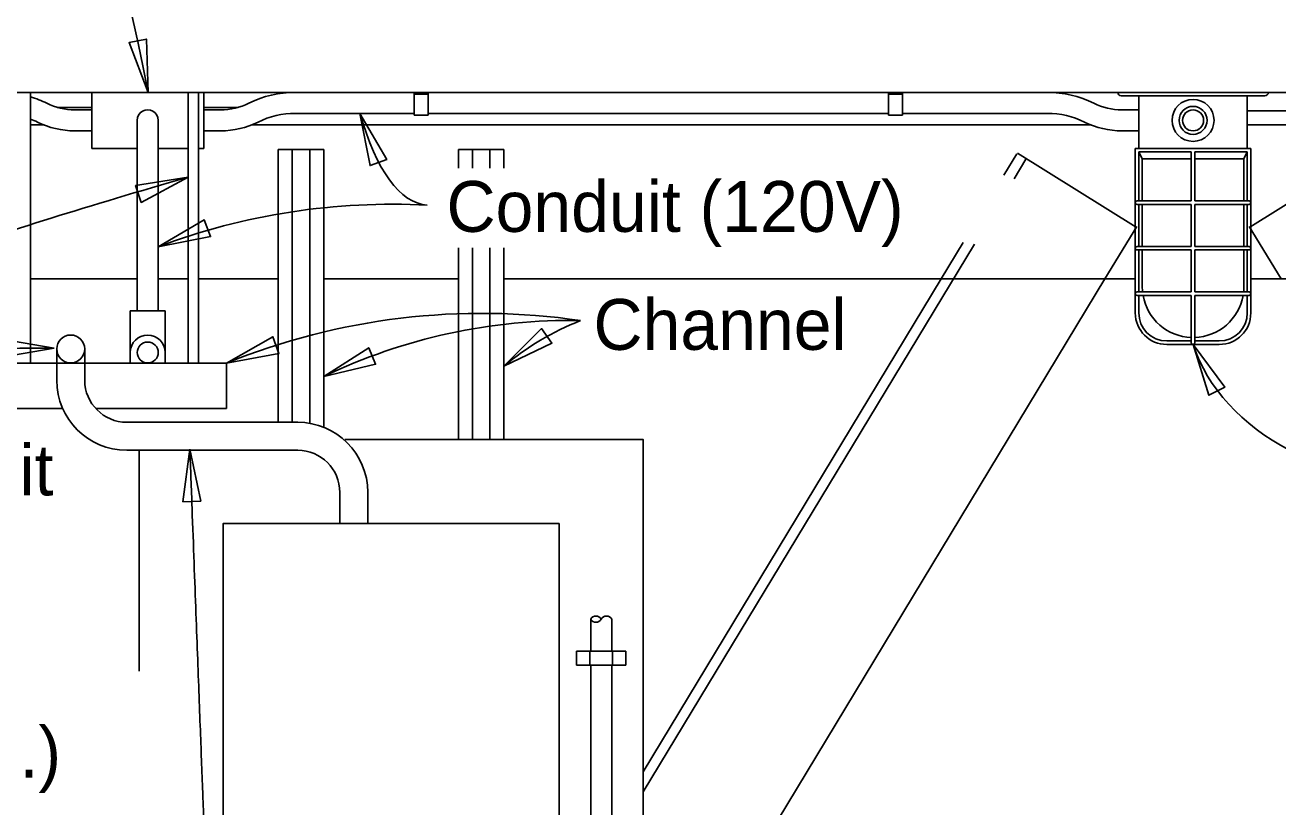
# Model space of a CAD drawing. Extents: x 112544 to 112597.1, y 111084 to 111107.1.
# Drawn here: x 112548.485 to 112552.213, y 111091.298 to 111093.624 of the extents above; entities that cross this region are included whole.
import ezdxf

# ---------------------------------------------------------------- set-up
doc = ezdxf.new("R2010")
doc.units = 0
for name, color, linetype in [('Dimension', 7, 'Continuous'), ('Lighting', 7, 'Continuous'), ('Miscellaneous', 7, 'Continuous'), ('SteelGirder', 7, 'Continuous'), ('SteelGirder_h', 7, 'Continuous'), ('TextStructures', 7, 'Continuous')]:
    doc.layers.add(name, color=color, linetype=linetype)

msp = doc.modelspace()

# ---------------------------------------------------------------- linework, layer by layer
at = {"layer": 'Dimension'}
for points in [[(112548.8513, 111093.4235), (112548.8463, 111093.5819), (112548.7945, 111093.5714)], [(112549.4811, 111093.361), (112549.5116, 111093.2056), (112549.5611, 111093.2243)], [(112548.9701, 111093.1717), (112548.8137, 111093.1461), (112548.8309, 111093.096)], [(112548.8814, 111092.9644), (112549.0369, 111092.9945), (112549.0183, 111093.0441)], [(112549.9097, 111092.6088), (112550.0524, 111092.6776), (112550.0218, 111092.7208)], [(112548.5722, 111092.6627), (112548.416, 111092.6892), (112548.416, 111092.6362)], [(112549.0845, 111092.6185), (112549.2404, 111092.6466), (112549.2225, 111092.6964)], [(112549.374, 111092.5785), (112549.5281, 111092.615), (112549.5075, 111092.6637)], [(112551.9599, 111092.6735), (112552.0073, 111092.5224), (112552.0544, 111092.5464)], [(112548.9755, 111092.3627), (112548.9548, 111092.2057), (112549.0077, 111092.2076)]]:
    msp.add_lwpolyline(points, close=True, dxfattribs=at)
for centre, radius, start, end in [((112549.5772, 111091.1108), 1.9799, 86.9707, 110.5746), ((112549.8441, 111090.7393), 2.0269, 81.6635, 112.0069), ((112550.105, 111091.058), 1.6871, 88.8828, 115.6789), ((112550.4424, 111091.9745), 0.8283, 111.5678, 130.0212)]:
    msp.add_arc(centre, radius, start, end, dxfattribs=at)
for centre, major_axis, ratio, start_param, end_param in [((112548.1769, 111092.198), (0.0332, -2.5173), 0.313255, 2.075166, 3.141607), ((112549.7608, 111094.1583), (0.079, 1.0703), 0.315754, 2.434073, 3.141613), ((112553.2613, 111093.1104), (1.3013, 0.4369), 0.58496, 3.141593, 4.152777)]:
    msp.add_ellipse(centre, major_axis=major_axis, ratio=ratio, start_param=start_param, end_param=end_param, dxfattribs=at)
for points, degree in [([(112548.9701, 111093.1717), (112548.6743, 111093.0852), (112548.1844, 111092.9372), (112547.674, 111092.7074), (112547.5362, 111092.5593), (112547.3473, 111092.2836), (112547.4514, 111091.9614), (112547.4271, 111091.7394), (112547.5394, 111091.7292)], 3), ([(112547.8143, 111092.3104), (112547.7556, 111092.3308), (112547.725, 111092.3819), (112547.85, 111092.5146), (112548.1741, 111092.6372), (112548.2992, 111092.6627), (112548.5722, 111092.6627)], 2), ([(112546.6152, 111090.8361), (112548.0879, 111090.8463), (112549.0316, 111090.8974), (112549.0112, 111091.3926), (112548.9755, 111092.3627)], 2)]:
    msp.add_open_spline(points, degree=degree, dxfattribs=at)
at = {"layer": 'Lighting'}
for p, q in [((112548.6835, 111093.4236), (112548.6835, 111093.2569)), ((112548.97, 111093.4236), (112548.6835, 111093.4236)), ((112549.0168, 111093.4236), (112549.0012, 111093.4236)), ((112549.0168, 111093.4236), (112549.0168, 111093.2569)), ((112549.643, 111093.4236), (112549.2888, 111093.4236)), ((112551.0543, 111093.4236), (112549.6847, 111093.4236)), ((112551.5259, 111093.4236), (112551.096, 111093.4236)), ((112551.736, 111093.4236), (112552.1839, 111093.4236)), ((112551.7464, 111093.4132), (112552.1735, 111093.4132)), ((112551.7985, 111093.4236), (112552.1214, 111093.4236)), ((112551.7985, 111093.4132), (112551.7985, 111093.2569)), ((112552.1214, 111093.4132), (112552.1214, 111093.2569)), ((112548.6835, 111093.3715), (112548.6331, 111093.3715)), ((112549.0168, 111093.3715), (112549.0671, 111093.3715)), ((112551.7985, 111093.3715), (112551.7482, 111093.3715)), ((112548.8189, 111093.3402), (112548.8189, 111092.774)), ((112548.8814, 111093.3402), (112548.8814, 111092.774)), ((112549.643, 111093.3611), (112549.2886, 111093.3611)), ((112551.0543, 111093.3611), (112549.6847, 111093.3611)), ((112551.5264, 111093.3611), (112551.096, 111093.3611)), ((112548.6835, 111093.309), (112548.6331, 111093.309)), ((112549.0168, 111093.309), (112549.0671, 111093.309)), ((112551.7985, 111093.309), (112551.7482, 111093.309)), ((112548.6835, 111093.2569), (112548.8189, 111093.2569)), ((112548.8814, 111093.2569), (112548.97, 111093.2569)), ((112549.0012, 111093.2569), (112549.0168, 111093.2569)), ((112549.2386, 111093.254), (112549.2386, 111092.4422)), ((112549.374, 111093.254), (112549.2386, 111093.254)), ((112549.2802, 111093.254), (112549.2802, 111092.4422)), ((112549.3324, 111093.254), (112549.3324, 111092.439)), ((112549.374, 111093.254), (112549.374, 111092.4272)), ((112549.9098, 111093.254), (112549.7744, 111093.254)), ((112549.7744, 111093.254), (112549.7744, 111093.1976)), ((112549.816, 111093.254), (112549.816, 111093.1976)), ((112549.8682, 111093.254), (112549.8682, 111093.1976)), ((112549.9098, 111093.254), (112549.9098, 111093.1976)), ((112551.7881, 111092.7673), (112551.7881, 111093.2569)), ((112551.7881, 111093.2569), (112551.7985, 111093.2569)), ((112551.7985, 111093.2569), (112552.1214, 111093.2569)), ((112551.7985, 111093.1007), (112551.7985, 111093.2465)), ((112551.7985, 111093.2465), (112551.9548, 111093.2465)), ((112551.8089, 111093.2257), (112551.7985, 111093.2465)), ((112551.8089, 111093.2257), (112551.9548, 111093.2257)), ((112551.9548, 111093.2465), (112551.9548, 111093.1007)), ((112551.9652, 111093.2465), (112552.1214, 111093.2465)), ((112551.9652, 111093.2465), (112551.9652, 111093.1007)), ((112551.9652, 111093.2257), (112552.111, 111093.2257)), ((112552.111, 111093.2257), (112552.1214, 111093.2465)), ((112552.1214, 111093.2569), (112552.1318, 111093.2569)), ((112552.1214, 111093.2465), (112552.1214, 111093.1007)), ((112552.1318, 111093.2569), (112552.1318, 111092.7673)), ((112551.9548, 111093.1007), (112551.7933, 111093.1007)), ((112551.9548, 111093.0903), (112551.7933, 111093.0903)), ((112551.7985, 111093.0903), (112551.7985, 111092.9652)), ((112551.9548, 111093.0903), (112551.9548, 111092.9652)), ((112551.9652, 111093.1007), (112552.1266, 111093.1007)), ((112551.9652, 111093.0903), (112552.1266, 111093.0903)), ((112551.9652, 111093.0903), (112551.9652, 111092.9652)), ((112552.1214, 111093.0903), (112552.1214, 111092.9652)), ((112549.7744, 111092.9608), (112549.7744, 111092.3909)), ((112549.816, 111092.9608), (112549.816, 111092.3909)), ((112549.8682, 111092.9608), (112549.8682, 111092.3909)), ((112549.9098, 111092.9608), (112549.9098, 111092.3909)), ((112551.9548, 111092.9652), (112551.7933, 111092.9652)), ((112551.9652, 111092.9652), (112552.1266, 111092.9652)), ((112551.9548, 111092.9548), (112551.7933, 111092.9548)), ((112551.7985, 111092.9548), (112551.7985, 111092.8298)), ((112551.9548, 111092.9548), (112551.9548, 111092.8298)), ((112551.9652, 111092.9548), (112552.1266, 111092.9548)), ((112551.9652, 111092.9548), (112551.9652, 111092.8298)), ((112552.1214, 111092.9548), (112552.1214, 111092.8298)), ((112551.9548, 111092.8298), (112551.7933, 111092.8298)), ((112551.9548, 111092.8194), (112551.7933, 111092.8194)), ((112551.7985, 111092.8194), (112551.7985, 111092.7673)), ((112551.9548, 111092.8194), (112551.9548, 111092.6788)), ((112551.9652, 111092.8298), (112552.1266, 111092.8298)), ((112551.9652, 111092.8194), (112552.1266, 111092.8194)), ((112551.9652, 111092.8194), (112551.9652, 111092.6788)), ((112552.1214, 111092.8194), (112552.1214, 111092.7673)), ((112548.7981, 111092.774), (112548.9022, 111092.774)), ((112548.7981, 111092.774), (112548.7981, 111092.6185)), ((112548.9022, 111092.774), (112548.9022, 111092.6185)), ((112551.8818, 111092.684), (112551.9548, 111092.684)), ((112551.8818, 111092.6736), (112552.0381, 111092.6736)), ((112551.9652, 111092.684), (112552.0381, 111092.684)), ((112548.5794, 111092.6602), (112548.5794, 111092.5672)), ((112548.6627, 111092.6602), (112548.6627, 111092.5673)), ((112548.3866, 111092.6185), (112549.0845, 111092.6185)), ((112549.0845, 111092.6185), (112549.0845, 111092.4831)), ((112548.5971, 111092.4831), (112548.3866, 111092.4831)), ((112549.0845, 111092.4831), (112548.6953, 111092.4831)), ((112549.2965, 111092.4422), (112548.7876, 111092.4423)), ((112548.7876, 111092.3589), (112549.2964, 111092.3588)), ((112549.4213, 111092.2338), (112549.4213, 111092.1409)), ((112549.5047, 111092.2339), (112549.5047, 111092.1409)), ((112550.1679, 111091.8565), (112550.1679, 111091.7614)), ((112550.2305, 111091.8565), (112550.2305, 111091.7614)), ((112550.1679, 111091.7197), (112550.1679, 111089.8121)), ((112550.2305, 111091.7197), (112550.2305, 111089.8121))]:
    msp.add_line(p, q, dxfattribs=at)
msp.add_lwpolyline([(112550.0742, 111092.1409), (112549.0742, 111092.1409), (112549.0742, 111089.3909), (112550.0742, 111089.3909)], close=True, dxfattribs=at)
for centre, radius in [((112551.96, 111093.3402), 0.0625), ((112551.96, 111093.3402), 0.0417), ((112551.96, 111093.3402), 0.0312), ((112548.621, 111092.6602), 0.0416), ((112548.8501, 111092.6498), 0.0312)]:
    msp.add_circle(centre, radius, dxfattribs=at)
for centre, radius, start, end in [((112548.4109, 111093.1111), 0.3125, 63.6116, 73.2157), ((112549.2894, 111093.1111), 0.3125, 90.0002, 116.3886), ((112551.5259, 111093.1111), 0.3125, 63.6115, 90.0001), ((112551.7464, 111093.4236), 0.0104, 180, 270), ((112552.1735, 111093.4236), 0.0104, 270, 0), ((112548.6331, 111093.559), 0.1875, 243.6116, 270.0001), ((112548.8501, 111093.3402), 0.0312, 359.9876, 180.0001), ((112549.0671, 111093.559), 0.1875, 270.0001, 296.3886), ((112551.7482, 111093.559), 0.1875, 243.6115, 270), ((112548.4109, 111093.1111), 0.25, 63.6116, 68.8407), ((112548.6331, 111093.559), 0.25, 243.6116, 270.0001), ((112549.0671, 111093.559), 0.25, 270.0001, 296.3886), ((112549.2894, 111093.1111), 0.25, 90.0002, 116.3886), ((112551.5259, 111093.1111), 0.25, 63.6115, 89.8816), ((112551.7482, 111093.559), 0.25, 243.6115, 270), ((112551.7933, 111093.0955), 0.0052, 89.9999, 270), ((112552.1266, 111093.0955), 0.0052, 270, 90.0001), ((112551.7933, 111092.96), 0.0052, 89.9999, 270), ((112552.1266, 111092.96), 0.0052, 270, 90.0001), ((112551.7933, 111092.8246), 0.0052, 89.9999, 270), ((112552.1266, 111092.8246), 0.0052, 270, 90.0001), ((112551.8818, 111092.7673), 0.0937, 180, 270), ((112551.8818, 111092.7673), 0.0833, 180, 270), ((112552.0381, 111092.7673), 0.0833, 270, 0), ((112552.0381, 111092.7673), 0.0937, 270, 0), ((112548.8501, 111092.6498), 0.052, 0.0163, 179.7051), ((112551.96, 111092.6788), 0.0052, 179.9665, 0), ((112548.7877, 111092.5672), 0.2083, 180, 269.9792), ((112548.7877, 111092.5673), 0.125, 180, 269.9792), ((112549.2964, 111092.2339), 0.2083, 0, 89.9792), ((112549.2963, 111092.2338), 0.125, 0, 89.9792), ((112550.1835, 111091.8478), 0.0179, 29.0027, 150.9974), ((112550.1835, 111091.8652), 0.0179, 209.003, 330.9971), ((112550.2148, 111091.8478), 0.0179, 29.0028, 150.9973)]:
    msp.add_arc(centre, radius, start, end, dxfattribs=at)
at = {"layer": 'Miscellaneous'}
for p, q in [((112547.2516, 111093.4236), (112552.7436, 111093.4236)), ((112551.8089, 111093.1007), (112551.8089, 111093.2257)), ((112552.111, 111093.2257), (112552.111, 111093.1007)), ((112551.8089, 111093.0903), (112551.8089, 111092.9652)), ((112552.111, 111093.0903), (112552.111, 111092.9652)), ((112551.8089, 111092.9548), (112551.8089, 111092.8454)), ((112552.111, 111092.9548), (112552.111, 111092.8454))]:
    msp.add_line(p, q, dxfattribs=at)
for start, end in [(180, 185.9203), (189.9053, 268.0265), (271.9735, 350.0947), (354.0797, 0)]:
    msp.add_arc((112551.96, 111092.8454), 0.151, start, end, dxfattribs=at)
at = {"layer": 'SteelGirder'}
for p, q in [((112548.5011, 111092.6185), (112548.5011, 111093.4236)), ((112548.97, 111092.6185), (112548.97, 111093.4236)), ((112549.0012, 111092.6185), (112549.0012, 111093.4236)), ((112549.643, 111093.4236), (112549.643, 111093.3559)), ((112549.643, 111093.4236), (112549.6847, 111093.4236)), ((112549.643, 111093.4184), (112549.6847, 111093.4184)), ((112549.6847, 111093.4236), (112549.6847, 111093.3559)), ((112551.0543, 111093.4236), (112551.0543, 111093.3559)), ((112551.096, 111093.4236), (112551.0543, 111093.4236)), ((112551.096, 111093.4184), (112551.0543, 111093.4184)), ((112551.096, 111093.4236), (112551.096, 111093.3559)), ((112548.5811, 111093.3789), (112548.6835, 111093.3788)), ((112549.0168, 111093.3788), (112549.1191, 111093.3788)), ((112549.6847, 111093.3559), (112549.643, 111093.3559)), ((112551.0543, 111093.3559), (112551.096, 111093.3559)), ((112552.1214, 111093.3686), (112552.7436, 111093.3686)), ((112548.5011, 111093.3269), (112548.5401, 111093.3269)), ((112549.1601, 111093.3269), (112551.6552, 111093.3269)), ((112552.1214, 111093.3269), (112552.7436, 111093.3269)), ((112548.5011, 111092.8685), (112548.8189, 111092.8685)), ((112548.8814, 111092.8685), (112548.97, 111092.8685)), ((112549.0012, 111092.8685), (112549.2386, 111092.8685)), ((112549.374, 111092.8685), (112549.7744, 111092.8685)), ((112549.9098, 111092.8685), (112551.7881, 111092.8685)), ((112550.3242, 111091.403), (112551.2107, 111092.8685)), ((112550.3242, 111090.5977), (112551.6978, 111092.8685)), ((112552.1318, 111092.8685), (112552.7436, 111092.8685)), ((112550.1259, 111091.7614), (112550.2725, 111091.7614)), ((112550.1259, 111091.7197), (112550.1259, 111091.7614)), ((112550.1653, 111091.7197), (112550.1653, 111091.7614)), ((112550.2331, 111091.7197), (112550.2331, 111091.7614)), ((112550.2725, 111091.7197), (112550.2725, 111091.7614)), ((112550.1259, 111091.7197), (112550.2725, 111091.7197))]:
    msp.add_line(p, q, dxfattribs=at)
for points in [[(112550.2018, 111089.1409), (112550.3242, 111089.1409), (112550.3242, 111092.3909), (112549.4361, 111092.3909)], [(112548.8242, 111092.3589), (112548.8242, 111091.7015)]]:
    msp.add_lwpolyline(points, dxfattribs=at)
at = {"layer": 'SteelGirder_h'}
for p, q in [((112551.3974, 111093.1772), (112551.4358, 111093.2407)), ((112551.4276, 111093.1668), (112551.4625, 111093.2245)), ((112551.4372, 111093.2429), (112551.7911, 111093.0227)), ((112552.4826, 111093.2429), (112552.1286, 111093.0227)), ((112551.6978, 111092.8685), (112551.7924, 111093.0249)), ((112552.2219, 111092.8685), (112552.1273, 111093.0249)), ((112550.3242, 111091.3427), (112551.31, 111092.9724)), ((112551.2107, 111092.8685), (112551.2763, 111092.977))]:
    msp.add_line(p, q, dxfattribs=at)

# ---------------------------------------------------------------- texts
at = {"layer": 'Dimension'}
for s, p in [('Conduit', (112547.8729, 111092.2247)), ('Rods (Typ.)', (112547.5362, 111091.3854))]:
    msp.add_text(s, height=0.1512, dxfattribs=at).set_placement(p)
at = {"layer": 'TextStructures'}
for s, p in [('Conduit (120V)', (112549.7389, 111093.0086)), ('Channel', (112550.1762, 111092.6577))]:
    msp.add_text(s, height=0.1512, dxfattribs=at).set_placement(p)

doc.saveas('drawing.dxf')
